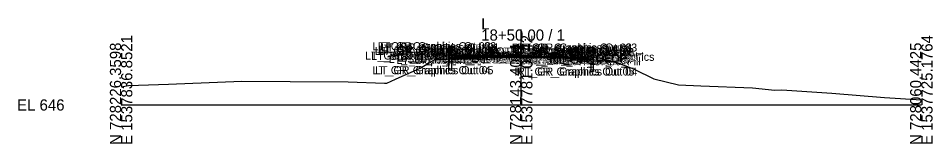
# Model space of a CAD drawing. Extents: x -26 to 1203, y -10 to 9522.
# Drawn here: x -25.7 to 202.8, y 9490.3 to 9521.7 of the extents above; entities that cross this region are included whole.
import ezdxf

# ---------------------------------------------------------------- set-up
doc = ezdxf.new("R2010")
doc.units = 0
for name, color, linetype in [('Default', 7, 'Continuous'), ('Exist CMT Pavement', 7, 'Continuous'), ('Exist Cross Section Cell', 7, 'Continuous'), ('Exist XS Center Line Elevation Label', 7, 'Continuous'), ('Exist XS Ground Line', 7, 'Continuous'), ('Old_Level_63', 7, 'Continuous'), ('Prop CMT Guardrail Graphics', 7, 'Continuous'), ('Prop CMT Pvmt Course 1', 7, 'Continuous'), ('Prop CMT Pvmt Course 1 Wedge', 7, 'Continuous'), ('Prop CMT Pvmt Course 2 Wedge', 7, 'Continuous'), ('Prop CMT Pvmt Course 3', 7, 'Continuous'), ('Prop CMT Pvmt Surface', 7, 'Continuous'), ('Prop CMT Pvmt Surface Shoulder', 7, 'Continuous'), ('Prop CMT Pvmt Wedge Surface 1', 7, 'Continuous'), ('Prop CMT Pvmt Wedge Surface 2', 7, 'Continuous'), ('Prop CMT Pvmt Wedge Surface 3', 7, 'Continuous'), ('Prop CMT Shld Paved Course 1', 7, 'Continuous'), ('Prop CMT Shld Paved Course 2', 7, 'Continuous'), ('Prop CMT Shld Paved Course 3', 7, 'Continuous'), ('Prop CMT Slope Grass', 7, 'Continuous'), ('Prop CMT Subgrade Earthwork', 7, 'Continuous'), ('Prop Superelevation  Arrow CELL', 7, 'Continuous'), ('Prop XS EOT Tick Mark', 7, 'Continuous'), ('Prop XS SE Text', 7, 'Continuous'), ('Prop XS Side Slope Text', 7, 'Continuous')]:
    doc.layers.add(name, color=color, linetype=linetype)

msp = doc.modelspace()

# ---------------------------------------------------------------- linework, layer by layer
at = {"layer": 'Exist CMT Pavement'}
for points in [[(100, 9511.99), (98.78, 9511.97), (97.32, 9511.95), (94.5, 9511.95), (90.22, 9511.95), (89, 9511.95)], [(100, 9511.99), (100.88, 9512), (101.22, 9512), (103.88, 9511.95), (105.5, 9511.91), (109.78, 9511.8), (111, 9511.77)]]:
    msp.add_lwpolyline(points, dxfattribs=at)
at = {"layer": 'Exist Cross Section Cell'}
for p, q in [((100, 9500), (100, 9518.89)), ((0, 9500), (100, 9500)), ((100, 9500), (200, 9500))]:
    msp.add_line(p, q, dxfattribs=at)
at = {"layer": 'Exist XS Ground Line'}
msp.add_lwpolyline([(0, 9504.52), (1.89, 9504.83), (11.86, 9505.2), (30.16, 9505.97), (42.28, 9505.85), (56.71, 9505.77), (65.83, 9505.49), (66.39, 9505.48), (68.59, 9506.48), (74.71, 9509.24), (78.23, 9511.25), (81.12, 9511.52), (87.21, 9511.95), (97.32, 9511.95), (100, 9511.99), (100.88, 9512), (103.88, 9511.95), (113.01, 9511.72), (122.6, 9510.95), (126.12, 9509.76), (128.23, 9508.97), (133.17, 9506.53), (139.31, 9505), (144.88, 9504.76), (157.78, 9504.26), (163.39, 9503.72), (165.14, 9503.78), (177.6, 9502.92), (190.78, 9501.89), (200, 9501.3)], dxfattribs=at)
at = {"layer": 'Prop CMT Guardrail Graphics'}
for points in [[(81.9, 9508.7), (81.9, 9514.7)], [(81.9, 9514.7), (83.23, 9514.7), (83.5, 9514.41)], [(83.5, 9513.82), (83.23, 9513.53), (82.57, 9513.53)], [(83.5, 9514.41), (83.23, 9514.12)], [(83.23, 9514.12), (83.5, 9513.82)], [(118.1, 9514.37), (116.77, 9514.37), (116.5, 9514.08)], [(116.5, 9514.08), (116.77, 9513.79)], [(118.1, 9508.37), (118.1, 9514.37)], [(82.57, 9513.53), (82.57, 9508.7)], [(116.77, 9513.79), (116.5, 9513.49)], [(116.5, 9513.49), (116.77, 9513.2), (117.43, 9513.2)], [(117.43, 9513.2), (117.43, 9508.37)], [(82.57, 9508.7), (81.9, 9508.7)], [(117.43, 9508.37), (118.1, 9508.37)]]:
    msp.add_lwpolyline(points, dxfattribs=at)
at = {"layer": 'Prop CMT Pvmt Course 1'}
for points in [[(100, 9512.37), (89, 9512.37)], [(89, 9512.37), (89, 9512.12), (89, 9512.12), (89, 9512.12)], [(89, 9512.12), (100, 9512.12)], [(100, 9512.12), (100, 9512.37)], [(100, 9512.37), (111, 9512.15)], [(100, 9512.12), (100, 9512.37)], [(111, 9511.9), (100, 9512.12)], [(111, 9512.15), (111, 9511.9), (111, 9511.9), (111, 9511.9)]]:
    msp.add_lwpolyline(points, dxfattribs=at)
at = {"layer": 'Prop CMT Pvmt Course 1 Wedge'}
for points in [[(89, 9512.12), (97.32, 9512.12), (100, 9512.12)], [(89, 9511.99), (89, 9512.12)], [(100, 9511.99), (97.32, 9511.99), (89, 9511.99)], [(100, 9512.12), (100, 9511.99)], [(100, 9512.12), (100.88, 9512.1), (103.88, 9512.04), (111, 9511.9)], [(100, 9511.99), (100, 9512.12)], [(111, 9511.77), (103.88, 9511.95), (100.88, 9512), (100.09, 9511.99), (100, 9511.99)], [(111, 9511.9), (111, 9511.77)]]:
    msp.add_lwpolyline(points, dxfattribs=at)
at = {"layer": 'Prop CMT Pvmt Course 2 Wedge'}
for points in [[(89, 9512.12), (97.32, 9512.12), (100, 9512.12)], [(89, 9511.95), (89, 9512.12)], [(100, 9511.99), (97.32, 9511.95), (89, 9511.95)], [(100, 9512.12), (100, 9511.99)], [(100, 9512.12), (100.88, 9512.1), (103.88, 9512.04), (111, 9511.9)], [(100, 9511.99), (100, 9512.12)], [(111, 9511.77), (103.88, 9511.95), (100.88, 9512), (100, 9511.99)], [(111, 9511.9), (111, 9511.77)]]:
    msp.add_lwpolyline(points, dxfattribs=at)
at = {"layer": 'Prop CMT Pvmt Course 3'}
for points in [[(89, 9511.91), (89, 9511.91), (89, 9511.53), (89, 9511.53)], [(89, 9511.53), (89, 9511.91)], [(111, 9511.69), (111, 9511.69), (111, 9511.31), (111, 9511.31)], [(111, 9511.31), (111, 9511.69)]]:
    msp.add_lwpolyline(points, dxfattribs=at)
at = {"layer": 'Prop CMT Pvmt Surface'}
for points in [[(100, 9512.37), (89, 9512.37)], [(100, 9512.37), (111, 9512.15)]]:
    msp.add_lwpolyline(points, dxfattribs=at)
at = {"layer": 'Prop CMT Pvmt Surface Shoulder'}
for points in [[(89, 9512.37), (83.51, 9512.37)], [(111, 9512.15), (116.48, 9512.04)]]:
    msp.add_lwpolyline(points, dxfattribs=at)
at = {"layer": 'Prop CMT Pvmt Wedge Surface 1'}
for points in [[(89, 9512.12), (89, 9512.37)], [(89, 9512.37), (89, 9512.37)], [(100, 9512.12), (89, 9512.12)], [(100, 9512.12), (111, 9511.9)], [(111, 9511.9), (111, 9512.15)], [(111, 9512.15), (111, 9512.15)]]:
    msp.add_lwpolyline(points, dxfattribs=at)
at = {"layer": 'Prop CMT Pvmt Wedge Surface 2'}
for points in [[(89, 9512.12), (89, 9512.37)], [(100, 9512.12), (89, 9512.12)], [(89, 9512.12), (89, 9512.12)], [(100, 9512.12), (111, 9511.9)], [(111, 9511.9), (111, 9512.15)], [(111, 9511.9), (111, 9511.9)]]:
    msp.add_lwpolyline(points, dxfattribs=at)
at = {"layer": 'Prop CMT Pvmt Wedge Surface 3'}
for points in [[(89, 9511.91), (89, 9512.37)], [(100, 9511.91), (89, 9511.91)], [(89, 9511.91), (89, 9511.91)], [(100, 9511.91), (111, 9511.69)], [(111, 9511.69), (111, 9512.15)], [(111, 9511.69), (111, 9511.69)]]:
    msp.add_lwpolyline(points, dxfattribs=at)
at = {"layer": 'Prop CMT Shld Paved Course 1'}
for points in [[(89, 9512.37), (83.51, 9512.37), (83.26, 9512.12)], [(83.26, 9512.12), (89, 9512.12)], [(89, 9512.12), (89, 9512.37)], [(111, 9512.15), (116.48, 9512.04), (116.74, 9511.78)], [(111, 9511.9), (111, 9512.15)], [(116.74, 9511.78), (111, 9511.9)]]:
    msp.add_lwpolyline(points, dxfattribs=at)
at = {"layer": 'Prop CMT Shld Paved Course 2'}
for points in [[(89, 9512.12), (83.26, 9512.12), (83.06, 9511.91)], [(83.06, 9511.91), (89, 9511.91)], [(89, 9511.91), (89, 9512.12)], [(111, 9511.9), (116.74, 9511.78), (116.95, 9511.57)], [(111, 9511.69), (111, 9511.9)], [(116.95, 9511.57), (111, 9511.69)]]:
    msp.add_lwpolyline(points, dxfattribs=at)
at = {"layer": 'Prop CMT Shld Paved Course 3'}
for points in [[(83.06, 9511.91), (82.68, 9511.53)], [(82.68, 9511.53), (89, 9511.53)], [(89, 9511.91), (83.06, 9511.91)], [(83.06, 9511.91), (83.06, 9511.91)], [(89, 9511.53), (89, 9511.91)], [(111, 9511.69), (116.95, 9511.57)], [(111, 9511.31), (111, 9511.69)], [(116.95, 9511.57), (116.95, 9511.57)], [(116.95, 9511.57), (117.33, 9511.19)], [(117.33, 9511.19), (111, 9511.31)]]:
    msp.add_lwpolyline(points, dxfattribs=at)
at = {"layer": 'Prop CMT Slope Grass'}
for points in [[(80.58, 9512.19), (78.26, 9511.25)], [(83.5, 9512.37), (80.58, 9512.19)], [(83.51, 9512.37), (83.5, 9512.37)], [(116.48, 9512.04), (116.5, 9512.04)], [(116.5, 9512.04), (119.42, 9511.8)], [(119.42, 9511.8), (122.6, 9510.95)]]:
    msp.add_lwpolyline(points, dxfattribs=at)
at = {"layer": 'Prop CMT Subgrade Earthwork'}
for points in [[(82.68, 9511.53), (81.94, 9512.27)], [(89, 9511.53), (82.68, 9511.53)], [(89, 9511.53), (89, 9511.95)], [(89, 9511.53), (89, 9511.53)], [(111, 9511.31), (111, 9511.77)], [(117.33, 9511.19), (118.06, 9511.91)], [(111, 9511.31), (117.33, 9511.19)], [(111, 9511.31), (111, 9511.31)]]:
    msp.add_lwpolyline(points, dxfattribs=at)
at = {"layer": 'Prop Superelevation  Arrow CELL'}
for p, q in [((97.07, 9512.94), (91.07, 9512.94)), ((103.05, 9512.82), (109.05, 9512.7))]:
    msp.add_line(p, q, dxfattribs=at)
msp.add_lwpolyline([(109.05, 9512.7), (107.56, 9513.23), (107.89, 9512.73)], close=True, dxfattribs=at)
at = {"layer": 'Prop XS EOT Tick Mark'}
for points in [[(89, 9512.37), (89, 9513.37)], [(111, 9512.15), (111, 9513.15)]]:
    msp.add_lwpolyline(points, dxfattribs=at)

# ---------------------------------------------------------------- texts
at = {"layer": 'Default'}
msp.add_text('-', height=0.0001, dxfattribs=at).set_placement((0, 9500))
msp.add_text('-', height=0.0001, dxfattribs=at).set_placement((0, 9500))
msp.add_text('-', height=0.0001, dxfattribs=at).set_placement((0, 9500))
at = {"layer": 'Exist Cross Section Cell'}
for s, p in [('L', (90, 9518.89)), ('18+50.00 / 1', (90, 9516.09)), ('EL 646', (-26, 9498.6))]:
    msp.add_text(s, height=2.8, dxfattribs=at).set_placement(p)
for s, p in [('E 1537836.8521', (2.8, 9490)), ('E 1537781.0142', (102.8, 9490)), ('E 1537725.1764', (202.8, 9490)), ('N 728226.3598', (0, 9490)), ('N 728143.4011', (100, 9490)), ('N 728060.4425', (200, 9490))]:
    msp.add_text(s, height=2.8, rotation=90, dxfattribs=at).set_placement(p)
at = {"layer": 'Exist XS Center Line Elevation Label'}
msp.add_text('657.99', height=0.75, dxfattribs=at).set_placement((98.45, 9510.82))
at = {"layer": 'Old_Level_63'}
for s, p in [('LT_GR_Graphics Out 03', (62.8, 9513.7)), ('LT_GR_Graphics Out 06', (63.42, 9512.53)), ('LT_GR_Graphics Out 02', (64.13, 9513.7)), ('LT_GR_Graphics Out 09', (64.13, 9513.12)), ('LT_GR_Graphics Out 07', (64.13, 9512.53)), ('LT_GR_Graphics Out 08', (64.4, 9512.82)), ('LT_GR_Graphics Out 01', (64.97, 9513.41)), ('LT_TM_OEOT', (79.94, 9512.37)), ('RT_GR_Graphics Out 08', (97.35, 9512.49)), ('RT_GR_Graphics Out 02', (97.62, 9513.37)), ('RT_GR_Graphics Out 09', (97.62, 9512.79)), ('RT_GR_Graphics Out 07', (97.62, 9512.2)), ('RT_GR_Graphics Out 01', (97.91, 9513.08)), ('RT_GR_Graphics Out 06', (98.24, 9512.2)), ('RT_GR_Graphics Out 03', (98.95, 9513.37)), ('RT_TM_OEOT', (101.9, 9512.15)), ('LT_GS_OS_GR_Face_Graphics', (60.96, 9511.37)), ('LT_Sub_Trench_Out_DLT', (62.51, 9511.27)), ('LT_Sub_Trench_Out', (66.89, 9510.53)), ('LT_Slope_Fill', (68.78, 9510.25)), ('LT_PS3_Shelf_Out', (69.04, 9510.91)), ('LT_GS_OS_CTL', (69.95, 9511.19)), ('LT_PS3_OEOP', (73.29, 9510.91)), ('LT_PS2_OEOP', (73.5, 9511.12)), ('LT_PV_Sub_Tie_Out', (73.95, 9510.95)), ('LT_PS1_OEOP', (74.32, 9511.37)), ('LT_PV1_OEEOP_Null', (75.46, 9511.37)), ('LT_PV_EG_TestPt3', (75.73, 9510.95)), ('LT_PV_OEEOP_EG', (76.54, 9510.95)), ('LT_PV1_OEEOP_W', (76.98, 9511.12)), ('LT_Sub_OEEOP', (78.21, 9510.53)), ('LT_PV2_OEEOP', (78.31, 9511.12)), ('LT_PV3_OEEOP', (78.31, 9510.91)), ('LT_Sub_OEOT', (79.08, 9510.53)), ('LT_PV2_OEOT', (79.17, 9511.12)), ('LT_PV3_OEOT', (79.17, 9510.91)), ('LT_PV1_OEOT', (79.74, 9511.37)), ('LT_PV_EG_TestPt2', (80.01, 9510.95)), ('LT_PV_EG_TestPt1', (84.86, 9510.97)), ('RT_PV_EG_TestPt1', (87.25, 9511)), ('RT_PV_EG_TestPt2', (90.96, 9510.91)), ('PV_EPGL_EG', (91.24, 9510.99)), ('PV2_PGL_W', (92.02, 9511.12)), ('PV3_PGL_W', (92.02, 9510.91)), ('PV1_PGL_W', (92.58, 9511.12)), ('RT_GS_OS_GR_Face_Graphics', (93.9, 9511.04)), ('PV1_PGL', (94.47, 9511.37)), ('RT_PV_EG_TestPt3', (95.24, 9510.8)), ('RT_PV_Sub_Tie_Out', (95.9, 9510.77)), ('RT_PV1_OEEOP_Null', (97.41, 9511.15)), ('RT_PV_OEEOP_EG', (98.49, 9510.77)), ('RT_Sub_Trench_Out_DLT', (98.58, 9510.91)), ('RT_PV1_OEEOP_W', (98.94, 9510.9)), ('RT_Sub_OEEOP', (100.17, 9510.31)), ('RT_PV2_OEEOP', (100.26, 9510.9)), ('RT_PV3_OEEOP', (100.26, 9510.69)), ('RT_Sub_OEOT', (101.03, 9510.31)), ('RT_PV2_OEOT', (101.13, 9510.9)), ('RT_PV3_OEOT', (101.13, 9510.69)), ('RT_Sub_Trench_Out', (101.49, 9510.19)), ('RT_PV1_OEOT', (101.69, 9511.15)), ('RT_PS3_Shelf_Out', (102.89, 9510.57)), ('RT_PS2_OEOP', (106.93, 9510.78)), ('RT_PS3_OEOP', (107.14, 9510.57)), ('RT_PS1_OEOP', (107.24, 9511.04)), ('RT_GS_OS_CTL', (108.74, 9510.8)), ('RT_Slope_Fill', (113.07, 9509.95)), ('LT_GR_Graphics Out 04', (62.8, 9507.7)), ('LT_GR_Graphics Out 05', (63.47, 9507.7)), ('RT_GR_Graphics Out 05', (98.28, 9507.37)), ('RT_GR_Graphics Out 04', (98.95, 9507.37))]:
    msp.add_text(s, height=2, dxfattribs=at).set_placement(p)
at = {"layer": 'Prop XS SE Text'}
msp.add_text('0.000', height=1, dxfattribs=at).set_placement((92.75, 9513.37))
msp.add_text('0.020', height=1, rotation=358.8542, dxfattribs=at).set_placement((103.77, 9513.29))
at = {"layer": 'Prop XS Side Slope Text'}
for s, rotation, p in [('2.48:1', 21.9642, (77.49, 9511.75)), ('3.75:1', 345.0668, (119.48, 9512.56))]:
    msp.add_text(s, height=1, rotation=rotation, dxfattribs=at).set_placement(p)

doc.saveas('drawing.dxf')
